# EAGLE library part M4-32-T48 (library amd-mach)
AMD MACH SERIES
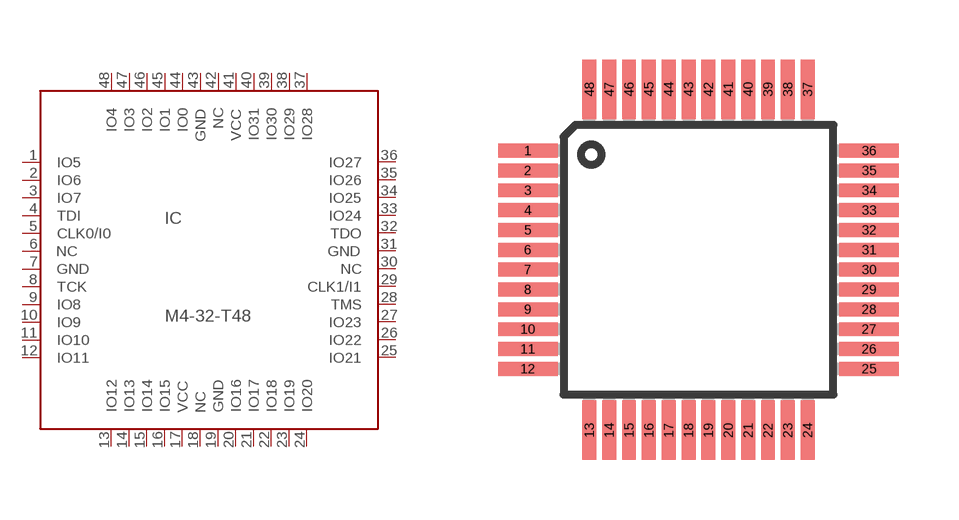
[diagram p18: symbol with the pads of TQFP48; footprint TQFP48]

Designator prefix IC

## M4-32-T48 (OC_FARNELL: unknown; OC_NEWARK: unknown)  [TQFP48]
1  IO5
2  IO6
3  IO7
4  TDI  in
5  CLK0/I0  in
6  NC  nc
7  GND  pwr
8  TCK  in
9  IO8
10  IO9
11  IO10
12  IO11
13  IO12
14  IO13
15  IO14
16  IO15
17  VCC  pwr
18  NC2  nc
19  GND  pwr
20  IO16
21  IO17
22  IO18
23  IO19
24  IO20
25  IO21
26  IO22
27  IO23
28  TMS  in
29  CLK1/I1  in
30  NC3  nc
31  GND  pwr
32  TDO  out
33  IO24
34  IO25
35  IO26
36  IO27
37  IO28
38  IO29
39  IO30
40  IO31
41  VCC  pwr
42  NC4  nc
43  GND  pwr
44  IO0
45  IO1
46  IO2
47  IO3
48  IO4

## Footprint TQFP48 (pad centres in mm)
THIN QUAD FLAT PACK
smd 1.5 x 0.35: 1 -4.3,2.75; 2 -4.3,2.25; 3 -4.3,1.75; 4 -4.3,1.25; 5 -4.3,0.75; 6 -4.3,0.25; 7 -4.3,-0.25; 8 -4.3,-0.75; 9 -4.3,-1.25; 10 -4.3,-1.75; 11 -4.3,-2.25; 12 -4.3,-2.75; 25 4.3,-2.75; 26 4.3,-2.25; 27 4.3,-1.75; 28 4.3,-1.25; 29 4.3,-0.75; 30 4.3,-0.25; 31 4.3,0.25; 32 4.3,0.75; 33 4.3,1.25; 34 4.3,1.75; 35 4.3,2.25; 36 4.3,2.75
smd 0.35 x 1.5: 13 -2.75,-4.3; 14 -2.25,-4.3; 15 -1.75,-4.3; 16 -1.25,-4.3; 17 -0.75,-4.3; 18 -0.25,-4.3; 19 0.25,-4.3; 20 0.75,-4.3; 21 1.25,-4.3; 22 1.75,-4.3; 23 2.25,-4.3; 24 2.75,-4.3; 37 2.75,4.3; 38 2.25,4.3; 39 1.75,4.3; 40 1.25,4.3; 41 0.75,4.3; 42 0.25,4.3; 43 -0.25,4.3; 44 -0.75,4.3; 45 -1.25,4.3; 46 -1.75,4.3; 47 -2.25,4.3; 48 -2.75,4.3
